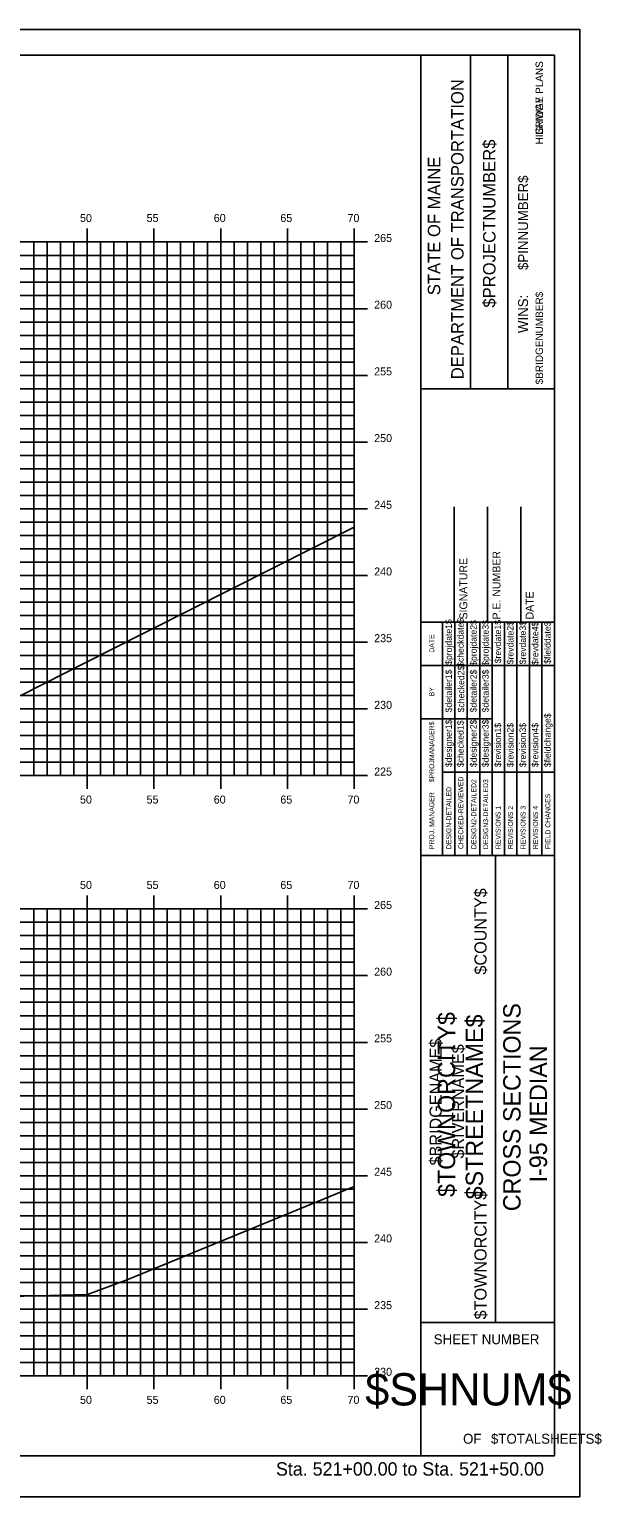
# Model space of a CAD drawing. Extents: x 1168600 to 1177589, y 610178 to 611246.
# Drawn here: x 1174885.5 to 1174928.4, y 610268.7 to 610378.7 of the extents above; entities that cross this region are included whole.
import ezdxf

# ---------------------------------------------------------------- set-up
doc = ezdxf.new("R2010")
doc.units = 0
for name, color, linetype in [('_Station Equation', 7, 'Continuous'), ('BORDER', 7, 'Continuous'), ('BRIDGE_TITLE', 7, 'Continuous'), ('H_V ANNOTATION', 7, 'Continuous'), ('HIGHWAY_TITLE', 7, 'Continuous'), ('MAJOR', 7, 'Continuous'), ('MINOR', 7, 'Continuous'), ('PLOT BOUNDARY', 7, 'Continuous')]:
    doc.layers.add(name, color=color, linetype=linetype)

msp = doc.modelspace()

# ---------------------------------------------------------------- linework, layer by layer
at = {"layer": '_Station Equation'}
for points in [[(1174884.88, 610328.8), (1174891.48, 610332.14), (1174909.85, 610341.42)], [(1174873.17, 610283.29), (1174884.14, 610283.75), (1174889.86, 610283.9), (1174892.88, 610285.03), (1174909.85, 610291.99)]]:
    msp.add_lwpolyline(points, dxfattribs=at)
at = {"layer": 'BORDER'}
for p, q in [((1174924.85, 610376.8), (1174764.85, 610376.8)), ((1174914.85, 610271.8), (1174914.85, 610376.8)), ((1174924.85, 610271.8), (1174924.85, 610376.8)), ((1174918.57, 610351.8), (1174918.57, 610376.8)), ((1174921.37, 610351.8), (1174921.37, 610376.8)), ((1174914.85, 610351.8), (1174924.85, 610351.8)), ((1174917.35, 610334.3), (1174917.35, 610342.95)), ((1174919.85, 610334.3), (1174919.85, 610342.95)), ((1174922.35, 610334.3), (1174922.35, 610342.95)), ((1174914.85, 610334.3), (1174924.85, 610334.3)), ((1174914.85, 610316.8), (1174924.85, 610316.8)), ((1174920.44, 610281.8), (1174920.44, 610316.8)), ((1174914.85, 610281.8), (1174924.85, 610281.8)), ((1174764.85, 610271.8), (1174924.85, 610271.8))]:
    msp.add_line(p, q, dxfattribs=at)
for points in [[(1174916.46, 610331.05), (1174916.46, 610334.3)], [(1174917.39, 610316.81), (1174917.39, 610334.3)], [(1174918.32, 610334.3), (1174918.32, 610316.81)], [(1174919.26, 610316.81), (1174919.26, 610334.3)], [(1174920.19, 610316.81), (1174920.19, 610334.3)], [(1174921.12, 610316.81), (1174921.12, 610334.3)], [(1174922.05, 610316.81), (1174922.05, 610334.3)], [(1174922.98, 610316.81), (1174922.98, 610334.3)], [(1174923.91, 610316.81), (1174923.91, 610334.3)], [(1174916.46, 610316.81), (1174916.46, 610333.6)], [(1174914.85, 610331.05), (1174924.85, 610331.05)], [(1174914.85, 610327.05), (1174916.46, 610327.05)], [(1174916.46, 610327.05), (1174920.19, 610327.05)], [(1174916.46, 610323.05), (1174924.85, 610323.05)]]:
    msp.add_lwpolyline(points, dxfattribs=at)
at = {"layer": 'MAJOR'}
for p, q in [((1174889.85, 610363.8), (1174889.85, 610362.8)), ((1174894.85, 610363.8), (1174894.85, 610362.8)), ((1174899.85, 610363.8), (1174899.85, 610362.8)), ((1174904.85, 610363.8), (1174904.85, 610362.8)), ((1174909.85, 610363.8), (1174909.85, 610362.8)), ((1174769.85, 610362.8), (1174909.85, 610362.8)), ((1174769.85, 610362.8), (1174909.85, 610362.8)), ((1174889.85, 610322.8), (1174889.85, 610362.8)), ((1174894.85, 610322.8), (1174894.85, 610362.8)), ((1174899.85, 610322.8), (1174899.85, 610362.8)), ((1174904.85, 610322.8), (1174904.85, 610362.8)), ((1174910.85, 610362.8), (1174908.84, 610362.8)), ((1174909.85, 610322.8), (1174909.85, 610362.8)), ((1174909.85, 610322.8), (1174909.85, 610362.8)), ((1174769.85, 610357.8), (1174909.85, 610357.8)), ((1174910.85, 610357.8), (1174908.84, 610357.8)), ((1174769.85, 610352.8), (1174909.85, 610352.8)), ((1174910.85, 610352.8), (1174908.84, 610352.8)), ((1174769.85, 610347.8), (1174909.85, 610347.8)), ((1174910.85, 610347.8), (1174908.84, 610347.8)), ((1174769.85, 610342.8), (1174909.85, 610342.8)), ((1174910.85, 610342.8), (1174908.84, 610342.8)), ((1174769.85, 610337.8), (1174909.85, 610337.8)), ((1174910.85, 610337.8), (1174908.84, 610337.8)), ((1174769.85, 610332.8), (1174909.85, 610332.8)), ((1174910.85, 610332.8), (1174908.84, 610332.8)), ((1174769.85, 610327.8), (1174909.85, 610327.8)), ((1174910.85, 610327.8), (1174908.84, 610327.8)), ((1174769.85, 610322.8), (1174909.85, 610322.8)), ((1174769.85, 610322.8), (1174909.85, 610322.8)), ((1174889.85, 610321.8), (1174889.85, 610322.8)), ((1174894.85, 610321.8), (1174894.85, 610322.8)), ((1174899.85, 610321.8), (1174899.85, 610322.8)), ((1174904.85, 610321.8), (1174904.85, 610322.8)), ((1174910.85, 610322.8), (1174908.84, 610322.8)), ((1174909.85, 610321.8), (1174909.85, 610322.8)), ((1174889.85, 610313.8), (1174889.85, 610312.8)), ((1174894.85, 610313.8), (1174894.85, 610312.8)), ((1174899.85, 610313.8), (1174899.85, 610312.8)), ((1174904.85, 610313.8), (1174904.85, 610312.8)), ((1174909.85, 610313.8), (1174909.85, 610312.8)), ((1174769.85, 610312.8), (1174909.85, 610312.8)), ((1174769.85, 610312.8), (1174909.85, 610312.8)), ((1174889.85, 610277.8), (1174889.85, 610312.8)), ((1174894.85, 610277.8), (1174894.85, 610312.8)), ((1174899.85, 610277.8), (1174899.85, 610312.8)), ((1174904.85, 610277.8), (1174904.85, 610312.8)), ((1174910.85, 610312.8), (1174908.84, 610312.8)), ((1174909.85, 610277.8), (1174909.85, 610312.8)), ((1174909.85, 610277.8), (1174909.85, 610312.8)), ((1174769.85, 610307.8), (1174909.85, 610307.8)), ((1174910.85, 610307.8), (1174908.84, 610307.8)), ((1174769.85, 610302.8), (1174909.85, 610302.8)), ((1174910.85, 610302.8), (1174908.84, 610302.8)), ((1174769.85, 610297.8), (1174909.85, 610297.8)), ((1174910.85, 610297.8), (1174908.84, 610297.8)), ((1174769.85, 610292.8), (1174909.85, 610292.8)), ((1174910.85, 610292.8), (1174908.84, 610292.8)), ((1174769.85, 610287.8), (1174909.85, 610287.8)), ((1174910.85, 610287.8), (1174908.84, 610287.8)), ((1174769.85, 610282.8), (1174909.85, 610282.8)), ((1174910.85, 610282.8), (1174908.84, 610282.8)), ((1174769.85, 610277.8), (1174909.85, 610277.8)), ((1174769.85, 610277.8), (1174909.85, 610277.8)), ((1174889.85, 610276.8), (1174889.85, 610277.8)), ((1174894.85, 610276.8), (1174894.85, 610277.8)), ((1174899.85, 610276.8), (1174899.85, 610277.8)), ((1174904.85, 610276.8), (1174904.85, 610277.8)), ((1174910.85, 610277.8), (1174908.84, 610277.8)), ((1174909.85, 610276.8), (1174909.85, 610277.8))]:
    msp.add_line(p, q, dxfattribs=at)
at = {"layer": 'MINOR'}
for p, q in [((1174885.85, 610322.8), (1174885.85, 610362.8)), ((1174886.85, 610322.8), (1174886.85, 610362.8)), ((1174887.85, 610322.8), (1174887.85, 610362.8)), ((1174888.85, 610322.8), (1174888.85, 610362.8)), ((1174890.85, 610322.8), (1174890.85, 610362.8)), ((1174891.85, 610322.8), (1174891.85, 610362.8)), ((1174892.85, 610322.8), (1174892.85, 610362.8)), ((1174893.85, 610322.8), (1174893.85, 610362.8)), ((1174895.85, 610322.8), (1174895.85, 610362.8)), ((1174896.85, 610322.8), (1174896.85, 610362.8)), ((1174897.85, 610322.8), (1174897.85, 610362.8)), ((1174898.85, 610322.8), (1174898.85, 610362.8)), ((1174900.85, 610322.8), (1174900.85, 610362.8)), ((1174901.85, 610322.8), (1174901.85, 610362.8)), ((1174902.85, 610322.8), (1174902.85, 610362.8)), ((1174903.85, 610322.8), (1174903.85, 610362.8)), ((1174905.85, 610322.8), (1174905.85, 610362.8)), ((1174906.85, 610322.8), (1174906.85, 610362.8)), ((1174907.85, 610322.8), (1174907.85, 610362.8)), ((1174908.85, 610322.8), (1174908.85, 610362.8)), ((1174769.85, 610361.8), (1174909.85, 610361.8)), ((1174909.85, 610361.8), (1174908.84, 610361.8)), ((1174769.85, 610360.8), (1174909.85, 610360.8)), ((1174909.85, 610360.8), (1174908.84, 610360.8)), ((1174769.85, 610359.8), (1174909.85, 610359.8)), ((1174909.85, 610359.8), (1174908.84, 610359.8)), ((1174769.85, 610358.8), (1174909.85, 610358.8)), ((1174909.85, 610358.8), (1174908.84, 610358.8)), ((1174769.85, 610356.8), (1174909.85, 610356.8)), ((1174909.85, 610356.8), (1174908.84, 610356.8)), ((1174769.85, 610355.8), (1174909.85, 610355.8)), ((1174769.85, 610354.8), (1174909.85, 610354.8)), ((1174909.85, 610355.8), (1174908.84, 610355.8)), ((1174909.85, 610354.8), (1174908.84, 610354.8)), ((1174769.85, 610353.8), (1174909.85, 610353.8)), ((1174909.85, 610353.8), (1174908.84, 610353.8)), ((1174769.85, 610351.8), (1174909.85, 610351.8)), ((1174909.85, 610351.8), (1174908.84, 610351.8)), ((1174769.85, 610350.8), (1174909.85, 610350.8)), ((1174909.85, 610350.8), (1174908.84, 610350.8)), ((1174769.85, 610349.8), (1174909.85, 610349.8)), ((1174909.85, 610349.8), (1174908.84, 610349.8)), ((1174769.85, 610348.8), (1174909.85, 610348.8)), ((1174909.85, 610348.8), (1174908.84, 610348.8)), ((1174769.85, 610346.8), (1174909.85, 610346.8)), ((1174909.85, 610346.8), (1174908.84, 610346.8)), ((1174769.85, 610345.8), (1174909.85, 610345.8)), ((1174909.85, 610345.8), (1174908.84, 610345.8)), ((1174769.85, 610344.8), (1174909.85, 610344.8)), ((1174769.85, 610343.8), (1174909.85, 610343.8)), ((1174909.85, 610344.8), (1174908.84, 610344.8)), ((1174909.85, 610343.8), (1174908.84, 610343.8)), ((1174769.85, 610341.8), (1174909.85, 610341.8)), ((1174909.85, 610341.8), (1174908.84, 610341.8)), ((1174769.85, 610340.8), (1174909.85, 610340.8)), ((1174909.85, 610340.8), (1174908.84, 610340.8)), ((1174769.85, 610339.8), (1174909.85, 610339.8)), ((1174909.85, 610339.8), (1174908.84, 610339.8)), ((1174769.85, 610338.8), (1174909.85, 610338.8)), ((1174909.85, 610338.8), (1174908.84, 610338.8)), ((1174769.85, 610336.8), (1174909.85, 610336.8)), ((1174909.85, 610336.8), (1174908.84, 610336.8)), ((1174769.85, 610335.8), (1174909.85, 610335.8)), ((1174909.85, 610335.8), (1174908.84, 610335.8)), ((1174769.85, 610334.8), (1174909.85, 610334.8)), ((1174909.85, 610334.8), (1174908.84, 610334.8)), ((1174769.85, 610333.8), (1174909.85, 610333.8)), ((1174909.85, 610333.8), (1174908.84, 610333.8)), ((1174769.85, 610331.8), (1174909.85, 610331.8)), ((1174909.85, 610331.8), (1174908.84, 610331.8)), ((1174769.85, 610330.8), (1174909.85, 610330.8)), ((1174909.85, 610330.8), (1174908.84, 610330.8)), ((1174769.85, 610329.8), (1174909.85, 610329.8)), ((1174909.85, 610329.8), (1174908.84, 610329.8)), ((1174769.85, 610328.8), (1174909.85, 610328.8)), ((1174909.85, 610328.8), (1174908.84, 610328.8)), ((1174769.85, 610326.8), (1174909.85, 610326.8)), ((1174909.85, 610326.8), (1174908.84, 610326.8)), ((1174769.85, 610325.8), (1174909.85, 610325.8)), ((1174909.85, 610325.8), (1174908.84, 610325.8)), ((1174769.85, 610324.8), (1174909.85, 610324.8)), ((1174909.85, 610324.8), (1174908.84, 610324.8)), ((1174769.85, 610323.8), (1174909.85, 610323.8)), ((1174909.85, 610323.8), (1174908.84, 610323.8)), ((1174885.85, 610277.8), (1174885.85, 610312.8)), ((1174886.85, 610277.8), (1174886.85, 610312.8)), ((1174887.85, 610277.8), (1174887.85, 610312.8)), ((1174888.85, 610277.8), (1174888.85, 610312.8)), ((1174890.85, 610277.8), (1174890.85, 610312.8)), ((1174891.85, 610277.8), (1174891.85, 610312.8)), ((1174892.85, 610277.8), (1174892.85, 610312.8)), ((1174893.85, 610277.8), (1174893.85, 610312.8)), ((1174895.85, 610277.8), (1174895.85, 610312.8)), ((1174896.85, 610277.8), (1174896.85, 610312.8)), ((1174897.85, 610277.8), (1174897.85, 610312.8)), ((1174898.85, 610277.8), (1174898.85, 610312.8)), ((1174900.85, 610277.8), (1174900.85, 610312.8)), ((1174901.85, 610277.8), (1174901.85, 610312.8)), ((1174902.85, 610277.8), (1174902.85, 610312.8)), ((1174903.85, 610277.8), (1174903.85, 610312.8)), ((1174905.85, 610277.8), (1174905.85, 610312.8)), ((1174906.85, 610277.8), (1174906.85, 610312.8)), ((1174907.85, 610277.8), (1174907.85, 610312.8)), ((1174908.85, 610277.8), (1174908.85, 610312.8)), ((1174769.85, 610311.8), (1174909.85, 610311.8)), ((1174769.85, 610310.8), (1174909.85, 610310.8)), ((1174909.85, 610311.8), (1174908.84, 610311.8)), ((1174909.85, 610310.8), (1174908.84, 610310.8)), ((1174769.85, 610309.8), (1174909.85, 610309.8)), ((1174909.85, 610309.8), (1174908.84, 610309.8)), ((1174769.85, 610308.8), (1174909.85, 610308.8)), ((1174909.85, 610308.8), (1174908.84, 610308.8)), ((1174769.85, 610306.8), (1174909.85, 610306.8)), ((1174909.85, 610306.8), (1174908.84, 610306.8)), ((1174769.85, 610305.8), (1174909.85, 610305.8)), ((1174909.85, 610305.8), (1174908.84, 610305.8)), ((1174769.85, 610304.8), (1174909.85, 610304.8)), ((1174909.85, 610304.8), (1174908.84, 610304.8)), ((1174769.85, 610303.8), (1174909.85, 610303.8)), ((1174909.85, 610303.8), (1174908.84, 610303.8)), ((1174769.85, 610301.8), (1174909.85, 610301.8)), ((1174909.85, 610301.8), (1174908.84, 610301.8)), ((1174769.85, 610300.8), (1174909.85, 610300.8)), ((1174769.85, 610299.8), (1174909.85, 610299.8)), ((1174909.85, 610300.8), (1174908.84, 610300.8)), ((1174909.85, 610299.8), (1174908.84, 610299.8)), ((1174769.85, 610298.8), (1174909.85, 610298.8)), ((1174909.85, 610298.8), (1174908.84, 610298.8)), ((1174769.85, 610296.8), (1174909.85, 610296.8)), ((1174909.85, 610296.8), (1174908.84, 610296.8)), ((1174769.85, 610295.8), (1174909.85, 610295.8)), ((1174909.85, 610295.8), (1174908.84, 610295.8)), ((1174769.85, 610294.8), (1174909.85, 610294.8)), ((1174909.85, 610294.8), (1174908.84, 610294.8)), ((1174769.85, 610293.8), (1174909.85, 610293.8)), ((1174909.85, 610293.8), (1174908.84, 610293.8)), ((1174769.85, 610291.8), (1174909.85, 610291.8)), ((1174909.85, 610291.8), (1174908.84, 610291.8)), ((1174769.85, 610290.8), (1174909.85, 610290.8)), ((1174909.85, 610290.8), (1174908.84, 610290.8)), ((1174769.85, 610289.8), (1174909.85, 610289.8)), ((1174769.85, 610288.8), (1174909.85, 610288.8)), ((1174909.85, 610289.8), (1174908.84, 610289.8)), ((1174909.85, 610288.8), (1174908.84, 610288.8)), ((1174769.85, 610286.8), (1174909.85, 610286.8)), ((1174909.85, 610286.8), (1174908.84, 610286.8)), ((1174769.85, 610285.8), (1174909.85, 610285.8)), ((1174909.85, 610285.8), (1174908.84, 610285.8)), ((1174769.85, 610284.8), (1174909.85, 610284.8)), ((1174909.85, 610284.8), (1174908.84, 610284.8)), ((1174769.85, 610283.8), (1174909.85, 610283.8)), ((1174909.85, 610283.8), (1174908.84, 610283.8)), ((1174769.85, 610281.8), (1174909.85, 610281.8)), ((1174909.85, 610281.8), (1174908.84, 610281.8)), ((1174769.85, 610280.8), (1174909.85, 610280.8)), ((1174909.85, 610280.8), (1174908.84, 610280.8)), ((1174769.85, 610279.8), (1174909.85, 610279.8)), ((1174909.85, 610279.8), (1174908.84, 610279.8)), ((1174769.85, 610278.8), (1174909.85, 610278.8)), ((1174909.85, 610278.8), (1174908.84, 610278.8))]:
    msp.add_line(p, q, dxfattribs=at)
at = {"layer": 'PLOT BOUNDARY'}
msp.add_lwpolyline([(1174756.75, 610268.74), (1174926.75, 610268.74), (1174926.75, 610378.74), (1174756.75, 610378.74)], close=True, dxfattribs=at)

# ---------------------------------------------------------------- texts
at = {"layer": 'BORDER'}
for s, height, rotation, p in [('DEPARTMENT OF TRANSPORTATION', 0.9318, 90, (1174918.05, 610352.51)), ('$PROJECTNUMBER$', 0.9318, 90, (1174920.44, 610357.88)), ('STATE OF MAINE', 0.9318, 90, (1174916.3, 610358.81)), ('$PINNUMBER$', 0.7453, 90, (1174922.88, 610360.7)), ('WINS:', 0.745, 90, (1174922.88, 610355.97)), ('P.E. NUMBER', 0.5906, 90, (1174920.81, 610334.5)), ('SIGNATURE', 0.591, 90, (1174918.33, 610334.5)), ('DATE', 0.591, 90, (1174923.29, 610334.5)), ('$projdate1$', 0.4845, 90, (1174917.17, 610331.1)), ('$checkdate$', 0.4845, 90, (1174918.06, 610330.95)), ('$projdate2$', 0.4845, 90, (1174919.03, 610331.03)), ('$projdate3$', 0.4845, 90, (1174919.93, 610331.03)), ('$revdate1$', 0.485, 90, (1174920.86, 610331.22)), ('$revdate2$', 0.485, 90, (1174921.79, 610331.14)), ('$revdate3$', 0.485, 90, (1174922.72, 610331.14)), ('$revdate4$', 0.485, 90, (1174923.65, 610331.1)), ('$fielddate$', 0.4845, 90, (1174924.58, 610331.18)), ('DATE', 0.371, 90, (1174915.85, 610332.01)), ('$detailer1$', 0.4845, 90, (1174917.17, 610327.54)), ('$checked2$', 0.485, 90, (1174918.1, 610327.54)), ('$detailer2$', 0.4845, 90, (1174919.03, 610327.54)), ('$detailer3$', 0.4845, 90, (1174919.93, 610327.54)), ('BY', 0.371, 90, (1174915.85, 610328.74)), ('$fieldchange$', 0.4845, 90, (1174924.58, 610323.43)), ('$PROJMANAGER$', 0.3727, 90, (1174915.85, 610322.3)), ('$designer1$', 0.4845, 90, (1174917.17, 610323.43)), ('$checked1$', 0.485, 90, (1174918.06, 610323.43)), ('$designer2$', 0.4845, 90, (1174919.03, 610323.43)), ('$designer3$', 0.4845, 90, (1174919.93, 610323.43)), ('$revision1$', 0.4845, 90, (1174920.86, 610323.43)), ('$revision2$', 0.4845, 90, (1174921.79, 610323.43)), ('$revision3$', 0.4845, 90, (1174922.72, 610323.43)), ('$revision4$', 0.4845, 90, (1174923.65, 610323.43)), ('CHECKED-REVIEWED', 0.3727, 90, (1174918.03, 610317.29)), ('DESIGN2-DETAILED2', 0.3727, 90, (1174919, 610317.29)), ('DESIGN3-DETAILED3', 0.3727, 90, (1174919.89, 610317.29)), ('PROJ. MANAGER', 0.3727, 90, (1174915.85, 610317.29)), ('DESIGN-DETAILED', 0.3727, 90, (1174917.13, 610317.29)), ('FIELD CHANGES', 0.3727, 90, (1174924.55, 610317.29)), ('REVISIONS 1', 0.3727, 90, (1174920.82, 610317.29)), ('REVISIONS 2', 0.3727, 90, (1174921.75, 610317.29)), ('REVISIONS 3', 0.3727, 90, (1174922.69, 610317.29)), ('REVISIONS 4', 0.3727, 90, (1174923.62, 610317.29)), ('CROSS SECTIONS', 1.3043, 90, (1174922.32, 610290.14)), ('I-95 MEDIAN', 1.3043, 90, (1174924.3, 610292.3)), ('SHEET NUMBER', 0.7453, 360, (1174915.81, 610280.17)), ('$SHNUM$', 2.419, 360, (1174910.68, 610275.58)), ('OF', 0.745, 360, (1174918.01, 610272.71)), ('$TOTALSHEETS$', 0.7453, 360, (1174920.1, 610272.71))]:
    msp.add_text(s, height=height, rotation=rotation, dxfattribs=at).set_placement(p)
at = {"layer": 'BRIDGE_TITLE'}
for s, height, p in [('BRIDGE PLANS', 0.559, (1174924, 610370.83)), ('$BRIDGENUMBER$', 0.559, (1174924, 610352.13)), ('$COUNTY$', 0.907, (1174919.77, 610307.88)), ('$BRIDGENAME$', 0.9072, (1174916.41, 610293.57)), ('$RIVERNAME$', 0.9072, (1174918.09, 610294.09)), ('$TOWNORCITY$', 0.9072, (1174919.77, 610282.03))]:
    msp.add_text(s, height=height, rotation=90, dxfattribs=at).set_placement(p)
at = {"layer": 'H_V ANNOTATION'}
for s, height, p in [('50', 0.6, (1174889.31, 610364.3)), ('55', 0.6, (1174894.3, 610364.3)), ('60', 0.6, (1174899.33, 610364.3)), ('65', 0.6, (1174904.32, 610364.3)), ('70', 0.6, (1174909.35, 610364.3)), ('265', 0.6, (1174911.35, 610362.8)), ('260', 0.6, (1174911.35, 610357.8)), ('255', 0.6, (1174911.35, 610352.8)), ('250', 0.6, (1174911.35, 610347.8)), ('245', 0.6, (1174911.35, 610342.8)), ('240', 0.6, (1174911.35, 610337.8)), ('235', 0.6, (1174911.35, 610332.8)), ('230', 0.6, (1174911.35, 610327.8)), ('225', 0.6, (1174911.35, 610322.8)), ('50', 0.6, (1174889.31, 610320.7)), ('55', 0.6, (1174894.3, 610320.7)), ('60', 0.6, (1174899.33, 610320.7)), ('65', 0.6, (1174904.32, 610320.7)), ('70', 0.6, (1174909.35, 610320.7)), ('50', 0.6, (1174889.31, 610314.3)), ('55', 0.6, (1174894.3, 610314.3)), ('60', 0.6, (1174899.33, 610314.3)), ('65', 0.6, (1174904.32, 610314.3)), ('70', 0.6, (1174909.35, 610314.3)), ('265', 0.6, (1174911.35, 610312.8)), ('260', 0.6, (1174911.35, 610307.8)), ('255', 0.6, (1174911.35, 610302.8)), ('250', 0.6, (1174911.35, 610297.8)), ('245', 0.6, (1174911.35, 610292.8)), ('240', 0.6, (1174911.35, 610287.8)), ('235', 0.6, (1174911.35, 610282.8)), ('230', 0.6, (1174911.35, 610277.8)), ('50', 0.6, (1174889.31, 610275.7)), ('55', 0.6, (1174894.3, 610275.7)), ('60', 0.6, (1174899.33, 610275.7)), ('65', 0.6, (1174904.32, 610275.7)), ('70', 0.6, (1174909.35, 610275.7)), ('Sta. 521+00.00 to Sta. 521+50.00', 1.0002, (1174903.99, 610270.32))]:
    msp.add_text(s, height=height, dxfattribs=at).set_placement(p)
at = {"layer": 'HIGHWAY_TITLE'}
for s, height, p in [('HIGHWAY PLANS', 0.559, (1174924, 610370.12)), ('$TOWNORCITY$', 1.3043, (1174917.42, 610291.21)), ('$STREETNAME$', 1.3043, (1174919.51, 610291.03))]:
    msp.add_text(s, height=height, rotation=90, dxfattribs=at).set_placement(p)

doc.saveas('drawing.dxf')
